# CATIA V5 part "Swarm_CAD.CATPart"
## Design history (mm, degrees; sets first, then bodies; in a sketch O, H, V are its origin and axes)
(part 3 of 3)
    distance L2 E3 = 15
    horizontal: L1 H, L3 H
    vertical: L2 V, L4 V
  Pad65: profile Sketch88, direction (0, 0, -1), length 192
  Sketch89 on end face of Pad51, origin (5055.8634, 0, -1213.8054), H (0, -1, 0), V (0.2334, 0, 0.9724)
    line L1 (-120, 1145.4414) -> (-59.7789, 1301.9134)
    line L2 (-59.7789, 1301.9134) -> (0, 1296.7668)
    point P3 (0, 1296.7668)
    line L3 (0, 1296.7668) -> (0, 1145.4414)
    line L4 (0, 1145.4414) -> (-120, 1145.4414)
    reference projected line E1 (-120, 1145.4414) -> (120, 1145.4414) from edge [face of Pad51 from Sketch66.L4 | end face of Pad51]
    reference projected line E2 (-78.762, 1252.5898) -> (-114.6804, 1159.2632) from edge [face of Pad51 from Sketch66.L3 | end face of Pad51]
    reference projected arc E3 centre (-0.0875, 1206.4414) radius 90 from (-0.0875, 1296.4414) to (-84.0815, 1238.7681) ccw from edge [face of Pad51 from Sketch66.A2 | end face of Pad51]
    length L2 = 60
    coincidence: P3 V, L4 E1, L1 E2
    vertical: L3 V
    horizontal: L4 H
    tangency: L2 E3
  Pad66: profile Sketch89, direction (-0.9724, 0, 0.2334), length 600
  Mirror32: of Pad66, about zx-plane
  Sketch90 on face of Mirror32, origin (4472.4414, 0, -1073.7382), H (0, -1, 0), V (0.2334, 0, 0.9724)
    line L1 (-120, 1145.4414) -> (-94.9835, 1210.4414)
    line L2 (-94.9835, 1210.4414) -> (94.9835, 1210.4414)
    line L3 (94.9835, 1210.4414) -> (120, 1145.4414)
    line L4 (120, 1145.4414) -> (-120, 1145.4414)
    reference projected line E1 (76.0903, 1145.4414) -> (-76.0903, 1145.4414) from edge [face of Mirror32 | face of Mirror2]
    reference projected line E2 (54.4593, 1315.7351) -> (114.6804, 1159.2632) from edge [face of Mirror32 | face of Mirror32]
    reference projected line E3 (-54.4593, 1315.7351) -> (-114.6804, 1159.2632) from edge [face of Pad66 from Sketch89.L1 | end face of Pad66]
    distance L2 L4 = 65
    horizontal: L2 H, L4 H
    coincidence: L4 E1, L3 E2, L1 E3
  Pad67: profile Sketch90, direction (-0.9724, 0, 0.2334), length 80
  Sketch91 on face of Pad34, origin (-2010, 0, 0), H (0, -1, 0), V (0, 0, 1)
    circle A1 centre (643.5, -160) radius 22.5
    reference projected circle E1 centre (643.5, -160) radius 22.5 from edge [face of Pad23 from Sketch30.A1 | face of Pad34]
    coincidence: A1 E1
  Pad68: profile Sketch91, direction (-1, 0, 0), length 60
  Sketch92 on face of Mirror30, origin (315.6888, -575.4594, -865.972), H (-0.8767, -0.481, 0), V (0.3833, -0.6987, 0.604)
    line L1 (-4371.7566, 1908.6399) -> (-4247.3214, 1946.2682)
    line L2 (-4247.3214, 1946.2682) -> (-4211.6687, 1828.366)
    line L3 (-4211.6687, 1828.366) -> (-4336.1039, 1790.7377)
    line L4 (-4336.1039, 1790.7377) -> (-4371.7566, 1908.6399)
    reference projected line E1 (-4398.7442, 1921.3735) -> (-4226.4493, 1973.4742) from edge [face of Mirror30 | face of Mirror30]
    reference projected line E2 (-4426.903, 2004.6358) -> (-4363.2245, 1794.0531) from edge [face of Mirror30 | face of Mirror30]
    reference projected line E3 (-4351.5135, 1765.1836) -> (-4179.2186, 1817.2842) from edge [face of Mirror30 | face of Mirror30]
    reference projected line E4 (-4231.9118, 1981.6804) -> (-4184.6811, 1825.4904) from edge [face of Mirror30 | face of Mirror30]
    distance L1 E1 = 20
    distance L4 E2 = 25
    distance L3 E3 = 20
    distance L2 E4 = 25
    perpendicularity: L2 L1
    parallelism: L3 L1, L4 L2
  Pocket21: profile Sketch92, direction (0.2905, -0.5296, -0.7969), length 40
  Mirror33: of Pocket21, about zx-plane
  Mirror34: of Pad68, about zx-plane
  Extract1: ExtractElem Mirror34
  Sketch93 on face of Mirror1, origin (0, 263.2631, 362.3506), H (-1, 0, 0), V (0, -0.809, 0.5878)
    construction line L1 through (0, 0) direction (1, 0)
    line L2 (-2844.2574, 144.728) -> (-1890, 144.728)
    construction line L3 through (0, 0) direction (0, 1)
    line L4 (-1890, 144.728) -> (-1890, -125.272)
    line L5 (-1890, -125.272) -> (-2240.2725, -125.272)
    line L6 (-2240.2725, -125.272) -> (-2240.2725, -35.272)
    line L7 (-2240.2725, -35.272) -> (-2558.5699, -35.272)
    line L8 (-2558.5699, -35.272) -> (-2558.5699, 54.728)
    line L9 (-2558.5699, 54.728) -> (-2844.2574, 54.728)
    line L10 (-2844.2574, 54.728) -> (-2844.2574, 144.728)
    point P1 (-1850, 144.728)
    line L11 (-1850, 144.728) -> (-782.5, 144.728)
    line L12 (-782.5, -125.272) -> (-1850, -125.272)
    line L13 (-782.5, 144.728) -> (-782.5, -125.272)
    line L14 (-1850, -125.272) -> (-1850, 144.728)
    line L15 (-1715.8627, -155.272) -> (-1715.8627, -245.272)
    line L16 (-1715.8627, -245.272) -> (-1433.2097, -245.272)
    line L17 (-1433.2097, -245.272) -> (-1433.2097, -335.272)
    line L18 (-1433.2097, -335.272) -> (-1069.0842, -335.272)
    line L19 (-1069.0842, -335.272) -> (-1069.0842, -425.272)
    line L20 (-1069.0842, -425.272) -> (-782.5, -425.272)
    line L21 (-782.5, -425.272) -> (-782.5, -155.272)
    point P2 (-602.5, 144.728)
    line L22 (-602.5, 144.728) -> (-317.271, 144.728)
    line L23 (-317.271, -125.272) -> (-602.5, -125.272)
    line L24 (-317.271, 144.728) -> (-317.271, -125.272)
    line L25 (-602.5, -125.272) -> (-602.5, 144.728)
    point P3 (-317.271, -125.272)
    line L26 (-2876.7362, -105.6676) -> (-1922.0492, -331.0454)
    line L27 (-1901.3708, -243.4531) -> (-2857.204, -17.8047)
    line L28 (-850.4962, -584.0124) -> (-1795.527, -360.9141)
    line L29 (-1774.8487, -273.3219) -> (-829.8179, -496.4201)
    line L30 (-1922.0492, -331.0454) -> (-1901.3708, -243.4531)
    line L31 (-1795.527, -360.9141) -> (-1774.8487, -273.3219)
    point P4 (-1901.3708, -243.4531)
    point P5 (-1890, -125.272)
    line L32 (-782.5, -155.272) -> (-1715.8627, -155.272)
    line L33 (-829.8179, -496.4201) -> (-850.4962, -584.0124)
    point P6 (-602.5, -155.272)
    line L34 (-602.5, -155.272) -> (-317.271, -155.272)
    line L35 (-317.271, -425.272) -> (-602.5, -425.272)
    line L36 (-317.271, -155.272) -> (-317.271, -425.272)
    line L37 (-602.5, -425.272) -> (-602.5, -155.272)
    point P7 (-317.271, -425.272)
    line L38 (-440, -456.272) -> (-40, -456.272)
    line L39 (-40, -571.272) -> (-440, -571.272)
    line L40 (-40, -456.272) -> (-40, -571.272)
    line L41 (-440, -571.272) -> (-440, -456.272)
    point P8 (-217.271, 144.728)
    line L42 (-217.271, 144.728) -> (832.729, 144.728)
    line L43 (832.729, -425.272) -> (-217.271, -425.272)
    line L44 (832.729, 144.728) -> (832.729, -425.272)
    line L45 (-217.271, -425.272) -> (-217.271, 144.728)
    point P9 (832.729, -425.272)
    point P10 (860, 144.728)
    line L46 (860, 144.728) -> (1910, 144.728)
    line L47 (1910, -425.272) -> (860, -425.272)
    line L48 (1910, 144.728) -> (1910, -425.272)
    line L49 (860, -425.272) -> (860, 144.728)
    point P11 (1910, -425.272)
    point P12 (310, -571.272)
    line L50 (310, -571.272) -> (1340, -571.272)
    line L51 (1340, -671.272) -> (310, -671.272)
    line L52 (1340, -571.272) -> (1340, -671.272)
    line L53 (310, -671.272) -> (310, -571.272)
    point P13 (310, -456.272)
    line L54 (310, -456.272) -> (530, -456.272)
    line L55 (530, -536.272) -> (310, -536.272)
    line L56 (530, -456.272) -> (530, -536.272)
    line L57 (310, -536.272) -> (310, -456.272)
    point P14 (630, -456.272)
    line L58 (630, -456.272) -> (850, -456.272)
    line L59 (850, -536.272) -> (630, -536.272)
    line L60 (850, -456.272) -> (850, -536.272)
    line L61 (630, -536.272) -> (630, -456.272)
    point P15 (850, -536.272)
    point P16 (950, -456.272)
    line L62 (950, -456.272) -> (1170, -456.272)
    line L63 (1170, -536.272) -> (950, -536.272)
    line L64 (1170, -456.272) -> (1170, -536.272)
    line L65 (950, -536.272) -> (950, -456.272)
    point P17 (1170, -536.272)
    point P18 (1270, -456.272)
    line L66 (1270, -456.272) -> (1490, -456.272)
    line L67 (1490, -536.272) -> (1270, -536.272)
    line L68 (1490, -456.272) -> (1490, -536.272)
    line L69 (1270, -536.272) -> (1270, -456.272)
    point P19 (1490, -536.272)
    point P20 (1170, -456.272)
    point P21 (0, 0)
    line L70 (-2857.204, -17.8047) -> (-2876.7362, -105.6676)
    distance L27 L26 = 90
    distance L29 L28 = 90
    distance L31 L30 = 130
    angle L30 L26 = 90
    distance L5 L2 = 270
    distance P5 P4 L1 = 11.3708
    length L8 = 90
    length L6 = 90
    distance L12 L11 = 270
    distance L32 L12 = 30
    distance L20 L32 = 270
    length L19 = 90
    length L17 = 90
    distance L21 L13 = 0
    angle L33 L28 = 90
    distance L14 L4 = 40
    distance L57 L56 = 220
    distance L61 L60 = 220
    distance L65 P20 = 220
    distance L69 L68 = 220
    distance L60 L65 = 100
    distance L64 L69 = 100
    distance L56 L61 = 100
    distance L55 L54 = 80
    distance L59 L50 = 35
    distance L45 L44 = 1050
    distance L49 L48 = 1050
    distance L45 L36 = 100
    horizontal: L2 L1, L5 L1, L7 L1, L9 L1, L11 L1, L12 L1, L16 L1, L18 L1, L20 L1, L22 L1, L23 L1, L34 L1, L35 L1, L38 L1, L39 L1, L42 L1, L43 L1, L46 L1, L47 L1, L50 L1, L51 L1, L54 L1, L55 L1, L58 L1, L59 L1, L62 L1, L63 L1, L66 L1, L67 L1
    vertical: L4 L3, L6 L3, L8 L3, L10 L3, L13 L3, L14 L3, L15 L3, L17 L3, L19 L3, L21 L3, L24 L3, L25 L3, L36 L3, L37 L3, L40 L3, L41 L3, L44 L3, L45 L3, L48 L3, L49 L3, L52 L3, L53 L3, L56 L3, L57 L3, L60 L3, L61 L3, L64 L3, L65 L3, L68 L3, L69 L3
    coincidence: P1 L2, P2 L2, P3 L12, P6 L25, P6 L32, P7 L24, P7 L20, P8 L2, P9 L35, P10 L2, P11 L35, P12 L39, P13 L53, P13 L38, P14 L38, P15 L55, P16 L38, P17 L55, P18 L38, P19 L55
  Pad69: profile Sketch93, direction (0, 0.5878, 0.809), length 10
  Sketch94 on end face of Pad69, origin (3403, 269.141, 370.4408), H (-0.5878, 0.6545, -0.4755), V (-0.809, -0.4755, 0.3455)
    point P1 (-825.75, -46.32)
    line L1 (-825.75, -46.32) -> (-113.815, 470.931)
    line L2 (-113.815, 470.931) -> (113.815, 470.931)
    line L3 (113.815, 470.931) -> (825.75, -46.32)
    point P4 (825.75, -46.32)
    line L4 (825.75, -46.32) -> (811.0554, -66.5454)
    point P5 (811.0554, -66.5454)
    line L5 (811.0554, -66.5454) -> (665, 39.57)
    point P6 (665, 39.57)
    line L6 (665, 39.57) -> (665, -300)
    line L7 (665, -300) -> (-665, -300)
    line L8 (-665, -300) -> (-665, 39.57)
    point P9 (-665, 39.57)
    line L9 (-665, 39.57) -> (-811.0554, -66.5454)
    point P10 (-811.0554, -66.5454)
    line L10 (-811.0554, -66.5454) -> (-825.75, -46.32)
    distance L7 H = 300
    distance P1 L7 = 253.68
    distance P4 L7 = 253.68
    distance L8 L6 = 1330
    distance L8 V = 665
    angle L1 V = 54
    angle L3 V = 54
    distance P1 P4 = 1651.5
    distance P6 P9 V = 0
    angle L5 L4 = 90
    distance P10 P5 V = 0
    distance L5 L3 = 25
    length L1 = 880
    horizontal: L2 H, L7 H
    vertical: L6 V, L8 V
    perpendicularity: L10 L1
    parallelism: L1 L9
  Mirror35: of Pad69, about zx-plane
  Sketch95 on end face of Pad69, origin (0, 269.141, 370.4408), H (-1, 0, 0), V (0, -0.809, 0.5878)
    line L1 (-2704.2574, 161.9212) -> (-2699.2574, 161.9212)
    line L2 (-2699.2574, 161.9212) -> (-2699.2574, -32.7041)
    line L3 (-2699.2574, -32.7041) -> (-2704.2574, -32.7041)
    line L4 (-2704.2574, -32.7041) -> (-2704.2574, 161.9212)
    line L5 (-2563.5699, -32.0096) -> (-2563.5699, 157.9904)
    line L6 (-2558.5699, 157.9904) -> (-2558.5699, -32.0096)
    line L7 (-2558.5699, -32.0096) -> (-2563.5699, -32.0096)
    line L8 (-2563.5699, 157.9904) -> (-2558.5699, 157.9904)
    reference projected line E1 (-2558.5699, 54.728) -> (-2558.5699, -35.272) from edge [face of Pad69 from Sketch93.L8 | end face of Pad69]
    line L9 (-2448.5699, -44.7326) -> (-2448.5699, 160)
    line L10 (-2443.5699, 148.3248) -> (-2443.5699, -41.6752)
    line L11 (-2448.5699, 160) -> (-2443.5699, 148.3248)
    line L12 (-2443.5699, -41.6752) -> (-2448.5699, -44.7326)
    line L13 (-2333.5699, -41.9996) -> (-2333.5699, 146.4384)
    line L14 (-2338.5699, 146.173) -> (-2338.5699, -41.8902)
    line L15 (-2333.5699, 146.4384) -> (-2338.5699, 146.173)
    line L16 (-2338.5699, -41.8902) -> (-2333.5699, -41.9996)
    point P17 (-2245.2725, 151.1255)
    line L17 (-2245.2725, 151.1255) -> (-2240.2725, 151.1255)
    line L18 (-2240.2725, 151.1255) -> (-2240.2725, -140.1003)
    line L19 (-2240.2725, -140.1003) -> (-2245.2725, -140.1003)
    line L20 (-2245.2725, -140.1003) -> (-2245.2725, 151.1255)
    line L21 (-2130.2725, 146.241) -> (-2125.2725, 146.241)
    line L22 (-2125.2725, 146.241) -> (-2125.2725, -142.1304)
    line L23 (-2125.2725, -142.1304) -> (-2130.2725, -142.1304)
    line L24 (-2130.2725, -142.1304) -> (-2130.2725, 146.241)
    line L25 (-2015.2725, 153.0203) -> (-2010.2725, 153.0203)
    line L26 (-2010.2725, 153.0203) -> (-2010.2725, -135.3512)
    line L27 (-2010.2725, -135.3512) -> (-2015.2725, -135.3512)
    line L28 (-2015.2725, -135.3512) -> (-2015.2725, 153.0203)
    line L29 (-1740, 148.9969) -> (-1735, 148.9969)
    line L30 (-1735, 148.9969) -> (-1735, -139.3745)
    line L31 (-1735, -139.3745) -> (-1740, -139.3745)
    line L32 (-1740, -139.3745) -> (-1740, 148.9969)
    line L33 (-1630, 155.7761) -> (-1625, 155.7761)
    line L34 (-1625, 155.7761) -> (-1625, -132.5953)
    line L35 (-1625, -132.5953) -> (-1630, -132.5953)
    line L36 (-1630, -132.5953) -> (-1630, 155.7761)
    line L37 (-1515, 148.9178) -> (-1510, 148.9178)
    line L38 (-1510, 148.9178) -> (-1510, -139.4537)
    line L39 (-1510, -139.4537) -> (-1515, -139.4537)
    line L40 (-1515, -139.4537) -> (-1515, 148.9178)
    line L41 (-1400, 148.4162) -> (-1395, 148.4162)
    line L42 (-1395, 148.4162) -> (-1395, -139.9552)
    line L43 (-1395, -139.9552) -> (-1400, -139.9552)
    line L44 (-1400, -139.9552) -> (-1400, 148.4162)
    line L45 (-1285, 149.7518) -> (-1289.0842, 149.7427)
    line L46 (-1289.0842, 149.7427) -> (-1289.0842, -138.6288)
    line L47 (-1289.0842, -138.6288) -> (-1285, -138.6288)
    line L48 (-1285, -138.6288) -> (-1285, 149.7518)
    line L49 (-1179.0842, 149.2411) -> (-1184.0842, 149.2411)
    line L50 (-1184.0842, 149.2411) -> (-1184.0842, -139.1303)
    line L51 (-1184.0842, -139.1303) -> (-1179.0842, -139.1303)
    line L52 (-1179.0842, -139.1303) -> (-1179.0842, 149.2411)
    line L53 (-1074.0842, 156.5219) -> (-1069.0842, 156.5219)
    line L54 (-1069.0842, 156.5219) -> (-1069.0842, -131.8496)
    line L55 (-1069.0842, -131.8496) -> (-1074.0842, -131.8496)
    line L56 (-1074.0842, -131.8496) -> (-1074.0842, 156.5219)
    line L57 (-959.0842, 151.8091) -> (-954.0842, 151.8091)
    line L58 (-954.0842, 151.8091) -> (-954.0842, -136.5624)
    line L59 (-954.0842, -136.5624) -> (-959.0842, -136.5624)
    line L60 (-959.0842, -136.5624) -> (-959.0842, 151.8091)
    line L61 (-864.0842, 151.3075) -> (-859.0842, 151.3075)
    line L62 (-859.0842, 151.3075) -> (-859.0842, -137.0639)
    line L63 (-859.0842, -137.0639) -> (-864.0842, -137.0639)
    line L64 (-864.0842, -137.0639) -> (-864.0842, 151.3075)
    reference projected line E2 (-2844.2574, 144.728) -> (-2844.2574, 54.728) from edge [face of Pad69 from Sketch93.L10 | end face of Pad69]
    reference projected line E3 (-2240.2725, -35.272) -> (-2240.2725, -125.272) from edge [face of Pad69 from Sketch93.L6 | end face of Pad69]
    reference projected line E4 (-1850, 144.728) -> (-1850, -125.272) from edge [face of Pad69 from Sketch93.L14 | end face of Pad69]
    point P65 (-1630, -142.1304)
    line L65 (-1630, -142.1304) -> (-1625, -142.1304)
    line L66 (-1625, -142.1304) -> (-1625, -260)
    line L67 (-1625, -260) -> (-1630, -260)
    line L68 (-1630, -260) -> (-1630, -142.1304)
    point P67 (-1625, -260)
    point P69 (-1515, -146.3943)
    line L69 (-1515, -146.3943) -> (-1510, -146.3943)
    line L70 (-1510, -146.3943) -> (-1510, -310)
    line L71 (-1510, -310) -> (-1515, -310)
    line L72 (-1515, -310) -> (-1515, -146.3943)
    point P71 (-1510, -310)
    point P73 (-1400, -146.3943)
    line L73 (-1400, -146.3943) -> (-1395, -146.3943)
    line L74 (-1395, -146.3943) -> (-1395, -350)
    line L75 (-1395, -350) -> (-1400, -350)
    line L76 (-1400, -350) -> (-1400, -146.3943)
    point P75 (-1395, -350)
    point P77 (-1285, -146.3943)
    line L77 (-1285, -146.3943) -> (-1289.0842, -146.3943)
    line L78 (-1289.0842, -146.3943) -> (-1289.0842, -360)
    line L79 (-1289.0842, -360) -> (-1285, -360)
    line L80 (-1285, -360) -> (-1285, -146.3943)
    point P79 (-1289.0842, -360)
    point P81 (-1179.0842, -146.3943)
    line L81 (-1179.0842, -146.3943) -> (-1184.0842, -146.3943)
    line L82 (-1184.0842, -146.3943) -> (-1184.0842, -370)
    line L83 (-1184.0842, -370) -> (-1179.0842, -370)
    line L84 (-1179.0842, -370) -> (-1179.0842, -146.3943)
    point P83 (-1184.0842, -370)
    point P85 (-1069.0842, -142.1304)
    line L85 (-1069.0842, -142.1304) -> (-1074.0842, -142.1304)
    line L86 (-1074.0842, -142.1304) -> (-1074.0842, -400)
    line L87 (-1074.0842, -400) -> (-1069.0842, -400)
    line L88 (-1069.0842, -400) -> (-1069.0842, -142.1304)
    reference projected line E5 (-1069.0842, -335.272) -> (-1069.0842, -425.272) from edge [face of Pad69 from Sketch93.L19 | end face of Pad69]
    point P89 (-959.0842, -146.3943)
    line L89 (-959.0842, -146.3943) -> (-954.0842, -146.3943)
    line L90 (-954.0842, -146.3943) -> (-954.0842, -430)
    line L91 (-954.0842, -430) -> (-959.0842, -430)
    line L92 (-959.0842, -430) -> (-959.0842, -146.3943)
    point P91 (-954.0842, -430)
    point P93 (-864.0842, -146.3943)
    line L93 (-864.0842, -146.3943) -> (-859.0842, -146.3943)
    line L94 (-859.0842, -146.3943) -> (-859.0842, -450)
    line L95 (-859.0842, -450) -> (-864.0842, -450)
    line L96 (-864.0842, -450) -> (-864.0842, -146.3943)
    point P95 (-859.0842, -450)
    point P97 (-510, -146.3943)
    line L97 (-510, -132.9567) -> (-510, 155.4147)
    line L98 (-505, -146.3943) -> (-505, -426.3943)
    line L99 (-510, -426.3943) -> (-510, -146.3943)
    line L100 (-505, 155.4147) -> (-505, -132.9567)
    point P98 (-505, -426.3943)
    point P99 (-415, -146.3943)
    line L101 (-415, -133.4583) -> (-415, 154.9132)
    line L102 (-415, -146.3943) -> (-410, -146.3943)
    line L103 (-410, -443.753) -> (-415, -443.753)
    line L104 (-410, -146.3943) -> (-410, -443.753)
    line L105 (-415, -443.753) -> (-415, -146.3943)
    line L106 (-410, 154.9132) -> (-410, -133.4583)
    point P100 (-410, -443.753)
    line L107 (-510, 155.4147) -> (-505, 155.4147)
    line L108 (-505, -132.9567) -> (-510, -132.9567)
    line L109 (-415, 154.9132) -> (-410, 154.9132)
    line L110 (-410, -133.4583) -> (-415, -133.4583)
    line L111 (-510, -146.3943) -> (-505, -146.3943)
    line L112 (-505, -426.3943) -> (-510, -426.3943)
    point P113 (-320, -450)
    line L113 (-320, -450) -> (-315, -450)
    line L114 (-315, -450) -> (-315, -590)
    line L115 (-315, -590) -> (-320, -590)
    line L116 (-320, -590) -> (-320, -450)
    line L117 (-185, -442.0433) -> (-185, -582.0433)
    line L118 (-190, -582.0433) -> (-190, -442.0433)
    line L119 (-190, -442.0433) -> (-185, -442.0433)
    line L120 (-185, -582.0433) -> (-190, -582.0433)
    point P121 (-107.271, 152.384)
    line L121 (-107.271, 152.384) -> (-102.271, 152.384)
    line L122 (-102.271, 152.384) -> (-102.271, -443.753)
    line L123 (-102.271, -443.753) -> (-107.271, -443.753)
    line L124 (-107.271, -443.753) -> (-107.271, 152.384)
    point P123 (-102.271, -443.753)
    line L125 (-2.271, 150.9154) -> (2.729, 150.227)
    line L126 (2.729, 150.227) -> (2.729, -445.91)
    line L127 (2.729, -445.91) -> (-2.271, -445.2216)
    line L128 (-2.271, -445.2216) -> (-2.271, 150.9154)
    line L129 (102.729, 168.1314) -> (107.729, 168.1314)
    line L130 (107.729, 168.1314) -> (107.729, -428.0057)
    line L131 (107.729, -428.0057) -> (102.729, -428.0057)
    line L132 (102.729, -428.0057) -> (102.729, 168.1314)
    line L133 (207.729, 148.7572) -> (212.729, 148.7572)
    line L134 (212.729, 148.7572) -> (212.729, -447.3798)
    line L135 (212.729, -447.3798) -> (207.729, -447.3798)
    line L136 (207.729, -447.3798) -> (207.729, 148.7572)
    line L137 (305, 152.125) -> (310, 152.125)
    line L138 (310, 152.125) -> (310, -444.0121)
    line L139 (310, -444.0121) -> (305, -444.0121)
    line L140 (305, -444.0121) -> (305, 152.125)
    line L141 (410, 150.008) -> (415, 150.008)
    line L142 (415, 150.008) -> (415, -715.1164)
    line L143 (415, -715.1164) -> (410, -715.1164)
    line L144 (410, -715.1164) -> (410, 150.008)
    reference projected line E6 (-217.271, 144.728) -> (-217.271, -425.272) from edge [face of Pad69 from Sketch93.L45 | end face of Pad69]
    reference projected line E7 (310, -456.272) -> (310, -536.272) from edge [face of Pad69 from Sketch93.L57 | end face of Pad69]
    line L145 (530, -719.2029) -> (530, 145.9214)
    line L146 (535, 145.9214) -> (535, -719.2029)
    line L147 (530, 145.9214) -> (535, 145.9214)
    line L148 (535, -719.2029) -> (530, -719.2029)
    line L149 (625, -724.6691) -> (625, 140.4553)
    line L150 (630, 139.2595) -> (630, -725.8648)
    line L151 (625, 140.4553) -> (630, 139.2595)
    line L152 (630, -725.8648) -> (625, -724.6691)
    line L153 (727.729, -705.94) -> (727.729, 159.1844)
    line L154 (732.729, 159.1844) -> (732.729, -705.94)
    line L155 (727.729, 159.1844) -> (732.729, 159.1844)
    line L156 (732.729, -705.94) -> (727.729, -705.94)
    line L157 (945, -717.3063) -> (945, 147.8181)
    line L158 (950, 155.1531) -> (950, -709.9713)
    line L159 (945, 147.8181) -> (950, 155.1531)
    line L160 (950, -709.9713) -> (945, -717.3063)
    line L161 (1065, -717.7143) -> (1065, 147.41)
    line L162 (1070, 147.41) -> (1070, -717.7143)
    line L163 (1065, 147.41) -> (1070, 147.41)
    line L164 (1070, -717.7143) -> (1065, -717.7143)
    line L165 (1170, -715.4619) -> (1170, 149.6625)
    line L166 (1175, 148.1014) -> (1175, -717.023)
    line L167 (1170, 149.6625) -> (1175, 148.1014)
    line L168 (1175, -717.023) -> (1170, -715.4619)
    line L169 (1265, -716.6782) -> (1265, 148.4462)
    line L170 (1270, 148.5427) -> (1270, -716.5816)
    line L171 (1265, 148.4462) -> (1270, 148.5427)
    line L172 (1270, -716.5816) -> (1265, -716.6782)
    line L173 (1385, -716.7043) -> (1385, 148.4201)
    line L174 (1390, 148.4201) -> (1390, -716.7043)
    line L175 (1385, 148.4201) -> (1390, 148.4201)
    line L176 (1390, -716.7043) -> (1385, -716.7043)
    line L177 (1490, -570) -> (1490, 156.8319)
    line L178 (1495, 156.8319) -> (1495, -570)
    line L179 (1490, 156.8319) -> (1495, 156.8319)
    line L180 (1495, -570) -> (1490, -570)
    line L181 (1595, -510) -> (1595, 155.2945)
    line L182 (1600, 155.2945) -> (1600, -510)
    line L183 (1595, 155.2945) -> (1600, 155.2945)
    line L184 (1600, -510) -> (1595, -510)
    line L185 (1700, -520) -> (1700, 156.0891)
    line L186 (1705, 156.0891) -> (1705, -520)
    line L187 (1700, 156.0891) -> (1705, 156.0891)
    line L188 (1705, -520) -> (1700, -520)
    line L189 (1805, -470) -> (1805, 145.7765)
    line L190 (1810, 145.7765) -> (1810, -470)
    line L191 (1805, 145.7765) -> (1810, 145.7765)
    line L192 (1810, -470) -> (1805, -470)
    reference projected line E8 (1910, -425.272) -> (1910, 144.728) from edge [face of Pad69 from Sketch93.L48 | end face of Pad69]
    reference projected line E9 (1270, -456.272) -> (1270, -536.272) from edge [face of Pad69 from Sketch93.L69 | end face of Pad69]
    reference projected line E10 (1170, -536.272) -> (1170, -456.272) from edge [face of Pad69 from Sketch93.L64 | end face of Pad69]
    reference projected line E11 (950, -456.272) -> (950, -536.272) from edge [face of Pad69 from Sketch93.L65 | end face of Pad69]
    reference projected line E12 (832.729, -425.272) -> (832.729, 144.728) from edge [face of Pad69 from Sketch93.L44 | end face of Pad69]
    reference projected line E13 (630, -456.272) -> (630, -536.272) from edge [face of Pad69 from Sketch93.L61 | end face of Pad69]
    reference projected line E14 (530, -536.272) -> (530, -456.272) from edge [face of Pad69 from Sketch93.L56 | end face of Pad69]
    point P193 (830, -570)
    line L193 (830, -570) -> (835, -570)
    line L194 (835, -570) -> (835, -690)
    line L195 (835, -690) -> (830, -690)
    line L196 (830, -690) -> (830, -570)
    line L197 (-2758.075, -32.7041) -> (-2782.6271, -143.1482)
    line L198 (-2782.6271, -143.1482) -> (-2777.505, -143.1482)
    line L199 (-2777.505, -143.1482) -> (-2752.953, -32.7041)
    line L200 (-2752.953, -32.7041) -> (-2758.075, -32.7041)
    reference projected line E15 (-2857.204, -17.8047) -> (-2876.7362, -105.6676) from edge [face of Pad69 from Sketch93.L70 | end face of Pad69]
    line L201 (-2680.6218, -168.1498) -> (-2675.4997, -168.1498)
    line L202 (-2656.0698, -57.7057) -> (-2680.6218, -168.1498)
    line L203 (-2675.4997, -168.1498) -> (-2650.9477, -57.7057)
    line L204 (-2650.9477, -57.7057) -> (-2656.0698, -57.7057)
    line L205 (-2578.7518, -193.7597) -> (-2573.6297, -193.7597)
    line L206 (-2554.1997, -83.3156) -> (-2578.7518, -193.7597)
    line L207 (-2573.6297, -193.7597) -> (-2549.0777, -83.3156)
    line L208 (-2549.0777, -83.3156) -> (-2554.1997, -83.3156)
    line L209 (-2475.3171, -212.3314) -> (-2470.1951, -212.3314)
    line L210 (-2450.7651, -101.8873) -> (-2475.3171, -212.3314)
    line L211 (-2470.1951, -212.3314) -> (-2445.643, -101.8873)
    line L212 (-2445.643, -101.8873) -> (-2450.7651, -101.8873)
    line L213 (-2373.5352, -238.3377) -> (-2368.4131, -238.3377)
    line L214 (-2348.9832, -127.8936) -> (-2373.5352, -238.3377)
    line L215 (-2368.4131, -238.3377) -> (-2343.8611, -127.8936)
    line L216 (-2343.8611, -127.8936) -> (-2348.9832, -127.8936)
    line L217 (-2271.9965, -265.438) -> (-2266.8744, -265.438)
    line L218 (-2247.4445, -154.9939) -> (-2271.9965, -265.438)
    line L219 (-2266.8744, -265.438) -> (-2242.3224, -154.9939)
    line L220 (-2242.3224, -154.9939) -> (-2247.4445, -154.9939)
    line L221 (-2168.6292, -284.3126) -> (-2163.5071, -284.3126)
    line L222 (-2144.0772, -173.8685) -> (-2168.6292, -284.3126)
    line L223 (-2163.5071, -284.3126) -> (-2138.9551, -173.8685)
    line L224 (-2138.9551, -173.8685) -> (-2144.0772, -173.8685)
    line L225 (-2075.7233, -304.1648) -> (-2070.6012, -304.1648)
    line L226 (-2051.1713, -193.7207) -> (-2075.7233, -304.1648)
    line L227 (-2070.6012, -304.1648) -> (-2046.0492, -193.7207)
    line L228 (-2046.0492, -193.7207) -> (-2051.1713, -193.7207)
    line L229 (-1998.4193, -328.1813) -> (-1993.2972, -328.1813)
    line L230 (-1973.8672, -217.7372) -> (-1998.4193, -328.1813)
    line L231 (-1993.2972, -328.1813) -> (-1967.3022, -218.0679)
    line L232 (-1967.3022, -218.0679) -> (-1973.8672, -217.7372)
    reference projected line E16 (-1922.0492, -331.0454) -> (-1901.3708, -243.4531) from edge [face of Pad69 from Sketch93.L30 | end face of Pad69]
    line L233 (-1708.9037, -397.9729) -> (-1703.7816, -397.9729)
    line L234 (-1605.5364, -416.8476) -> (-1600.4144, -416.8476)
    line L235 (-1512.6305, -436.6997) -> (-1507.5085, -436.6997)
    line L236 (-1435.3265, -460.7162) -> (-1430.2044, -460.7162)
    line L237 (-1703.7816, -397.9729) -> (-1679.2296, -287.5288)
    line L238 (-1580.9844, -306.4035) -> (-1605.5364, -416.8476)
    line L239 (-1600.4144, -416.8476) -> (-1575.8623, -306.4035)
    line L240 (-1488.0785, -326.2557) -> (-1512.6305, -436.6997)
    line L241 (-1684.3517, -287.5288) -> (-1708.9037, -397.9729)
    line L242 (-1679.2296, -287.5288) -> (-1684.3517, -287.5288)
    line L243 (-1575.8623, -306.4035) -> (-1580.9844, -306.4035)
    line L244 (-1507.5085, -436.6997) -> (-1482.9564, -326.2557)
    line L245 (-1482.9564, -326.2557) -> (-1488.0785, -326.2557)
    line L246 (-1410.7744, -350.2721) -> (-1435.3265, -460.7162)
    line L247 (-1430.2044, -460.7162) -> (-1404.2094, -350.6028)
    line L248 (-1404.2094, -350.6028) -> (-1410.7744, -350.2721)
    line L249 (-1349.0488, -481.0968) -> (-1343.9268, -481.0968)
    line L250 (-1245.6815, -499.9714) -> (-1240.5595, -499.9714)
    line L251 (-1152.7756, -519.8236) -> (-1147.6536, -519.8236)
    line L252 (-1075.4716, -543.8401) -> (-1070.3495, -543.8401)
    line L253 (-1343.9268, -481.0968) -> (-1319.3747, -370.6527)
    line L254 (-1221.1295, -389.5273) -> (-1245.6815, -499.9714)
    line L255 (-1240.5595, -499.9714) -> (-1216.0074, -389.5273)
    line L256 (-1128.2236, -409.3795) -> (-1152.7756, -519.8236)
    line L257 (-1324.4968, -370.6527) -> (-1349.0488, -481.0968)
    line L258 (-1319.3747, -370.6527) -> (-1324.4968, -370.6527)
    line L259 (-1216.0074, -389.5273) -> (-1221.1295, -389.5273)
    line L260 (-1147.6536, -519.8236) -> (-1123.1016, -409.3795)
    line L261 (-1123.1016, -409.3795) -> (-1128.2236, -409.3795)
    line L262 (-1050.9196, -433.396) -> (-1075.4716, -543.8401)
    line L263 (-1070.3495, -543.8401) -> (-1044.3545, -433.7267)
    line L264 (-1044.3545, -433.7267) -> (-1050.9196, -433.396)
    line L265 (-1003.8652, -564.4387) -> (-998.7431, -564.4387)
    line L266 (-926.5611, -588.4552) -> (-921.4391, -588.4552)
    line L267 (-979.3131, -453.9946) -> (-1003.8652, -564.4387)
    line L268 (-998.7431, -564.4387) -> (-974.1911, -453.9946)
    line L269 (-974.1911, -453.9946) -> (-979.3131, -453.9946)
    line L270 (-902.0091, -478.0111) -> (-926.5611, -588.4552)
    line L271 (-921.4391, -588.4552) -> (-895.444, -478.3418)
    line L272 (-895.444, -478.3418) -> (-902.0091, -478.0111)
    reference projected line E17 (-1433.2097, -245.272) -> (-1433.2097, -335.272) from edge [face of Pad69 from Sketch93.L17 | end face of Pad69]
    distance L2 L4 = 5
    distance L6 E1 = 0
    distance L20 L18 = 5
    distance L4 E2 = 140
    distance L5 L2 = 135.6875
    distance L9 L6 = 110
    distance L13 L10 = 110
    distance L10 L9 = 5
    distance L14 L13 = 5
    distance L18 E3 = 0
    distance L24 L18 = 110
    distance L28 L22 = 110
    distance L26 L28 = 5
    distance L32 E4 = 110
    distance L30 L32 = 5
    distance L36 L32 = 110
    distance L40 L34 = 110
    distance L44 L38 = 110
    distance L48 L42 = 110
    distance L52 L46 = 110
    distance L56 L50 = 110
    distance L60 L54 = 110
    distance L64 L58 = 90
    distance L88 L86 = 5
    distance L88 E5 = 0
    distance L56 L86 = 0
    distance L52 L50 = 5
    distance L114 L116 = 5
    distance L124 E6 = 110
    distance L122 L124 = 5
    distance L128 L126 = 5
    distance L128 L122 = 100
    distance L132 L130 = 5
    distance L132 L126 = 100
    distance L136 L134 = 5
    distance L136 L130 = 100
    distance L140 L138 = 5
    distance L140 E7 = 5
    distance L144 L138 = 100
    distance L142 L144 = 5
    distance L146 L145 = 5
    distance L150 L149 = 5
    distance L154 L153 = 5
    distance L158 L157 = 5
    distance L162 L161 = 5
    distance L166 L165 = 5
    distance L170 L169 = 5
    distance L174 L173 = 5
    distance L178 L177 = 5
    distance L182 L181 = 5
    distance L186 L185 = 5
    distance L190 L189 = 5
    distance L190 E8 = 100
    distance L186 L189 = 100
    distance L182 L185 = 100
    distance L178 L181 = 100
    distance L174 L177 = 100
    distance L170 E9 = 0
    distance L165 E10 = 0
    distance L162 L165 = 100
    distance L158 E11 = 0
    distance L154 E12 = 100
    distance L150 E13 = 0
    distance L145 E14 = 0
    distance L196 L194 = 5
    distance L197 L199 = 5
    distance L200 L198 = 110.4441
    distance L197 E15 = 100
    distance L202 L199 = 100
    distance L206 L203 = 100
    distance L210 L207 = 100
    distance L214 L211 = 100
    distance L218 L215 = 100
    distance L222 L219 = 100
    distance L226 L223 = 90
    distance L231 E16 = 70
    distance L238 L237 = 100
    distance L240 L239 = 90
    distance L254 L253 = 100
    distance L256 L255 = 90
    distance L76 E17 = 33.2097
    horizontal: L1 H, L3 H, L17 H, L19 H, L65 H, L67 H, L69 H, L71 H, L73 H, L75 H, L77 H, L79 H, L81 H, L83 H, L85 H, L87 H, L89 H, L91 H, L93 H, L95 H, L102 H, L103 H, L113 H, L115 H, L121 H, L123 H, L193 H, L195 H, L198 H, L201 H, L205 H, L209 H, L213 H, L217 H, L221 H, L225 H, L229 H, L233 H, L234 H, L235 H, L236 H, L249 H, L250 H, L251 H, L252 H, L265 H, L266 H
    vertical: L2 V, L4 V, L18 V, L20 V, L66 V, L68 V, L70 V, L72 V, L74 V, L76 V, L78 V, L80 V, L82 V, L84 V, L86 V, L88 V, L90 V, L92 V, L94 V, L96 V, L98 V, L99 V, L104 V, L105 V, L114 V, L116 V, L117 V, L118 V, L122 V, L124 V, L194 V, L196 V
    coincidence: P17 L15, P65 L36, P65 L23, P67 L34, P69 L40, P71 L38, P73 L69, P73 L44, P75 L42, P77 L69, P77 L48, P79 L46, P81 L69, P81 L52, P83 L50, P85 L23, P89 L69, P89 L60, P91 L58, P93 L69, P93 L64, P95 L62, P97 L69, P97 L97, P98 L100, P99 L69, P99 L101, P100 L106, P113 L95, P121 L45, P123 L103, P193 L180
  Pocket22: profile Sketch95, direction (0, -0.5878, -0.809), length 10
  Mirror36: of Pocket22, about zx-plane
  Sketch96 on end face of Pad69, origin (0, 269.141, 370.4408), H (-1, 0, 0), V (0, -0.809, 0.5878)
    line L1 (-2860, 99.728) -> (1930, 99.728)
    line L2 (1930, 99.728) -> (1930, 94.728)
    line L3 (1930, 94.728) -> (-2860, 94.728)
    line L4 (-2860, 94.728) -> (-2860, 99.728)
    reference projected line E1 (-2844.2574, 54.728) -> (-2558.5699, 54.728) from edge [face of Pad69 from Sketch93.L9 | end face of Pad69]
    line L5 (-2570, 55) -> (1940, 55)
    line L6 (1940, 55) -> (1940, 50)
    line L7 (1940, 50) -> (-2570, 50)
    line L8 (-2570, 50) -> (-2570, 55)
    point P9 (7.9407, -80)
    line L9 (-2562.0593, 10) -> (1947.9407, 10)
    line L10 (1947.9407, 10) -> (1947.9407, 5)
    line L11 (1947.9407, 5) -> (-2562.0593, 5)
    line L12 (-2562.0593, 5) -> (-2562.0593, 10)
    point P14 (320.9791, -120)
    line L13 (-2249.0209, -35) -> (2260.9791, -35)
    line L14 (2260.9791, -35) -> (2260.9791, -40)
    line L15 (2260.9791, -40) -> (-2249.0209, -40)
    line L16 (-2249.0209, -40) -> (-2249.0209, -35)
    point P19 (726.8307, -250)
    line L17 (-1843.1693, -195.272) -> (2666.8307, -195.272)
    line L18 (2666.8307, -195.272) -> (2666.8307, -200.272)
    line L19 (2666.8307, -200.272) -> (-1843.1693, -200.272)
    line L20 (-1843.1693, -200.272) -> (-1843.1693, -195.272)
    point P24 (1025.3837, -300)
    line L21 (-1544.6163, -245.272) -> (2965.3837, -245.272)
    line L22 (2965.3837, -245.272) -> (2965.3837, -250.272)
    line L23 (2965.3837, -250.272) -> (-1544.6163, -250.272)
    line L24 (-1544.6163, -250.272) -> (-1544.6163, -245.272)
    point P29 (1215.4979, -400)
    line L25 (-1354.5021, -335.272) -> (3155.4979, -335.272)
    line L26 (3155.4979, -335.272) -> (3155.4979, -340.272)
    line L27 (3155.4979, -340.272) -> (-1354.5021, -340.272)
    line L28 (-1354.5021, -340.272) -> (-1354.5021, -335.272)
    reference projected line E2 (-782.5, -155.272) -> (-1715.8627, -155.272) from edge [face of Pad69 from Sketch93.L32 | end face of Pad69]
    reference projected line E3 (-1715.8627, -245.272) -> (-1433.2097, -245.272) from edge [face of Pad69 from Sketch93.L16 | end face of Pad69]
    point P34 (-2.5256, -120)
    line L29 (-2259.4872, -80) -> (2250.5128, -80)
    line L30 (2250.5128, -80) -> (2250.5128, -85)
    line L31 (2250.5128, -85) -> (-2259.4872, -85)
    line L32 (-2259.4872, -85) -> (-2259.4872, -80)
    point P39 (928.5636, -245)
    line L33 (-1451.3221, -290.272) -> (3058.6779, -290.272)
    line L34 (3058.6779, -290.272) -> (3058.6779, -295.272)
    line L35 (3058.6779, -295.272) -> (-1451.3221, -295.272)
    line L36 (-1451.3221, -295.272) -> (-1451.3221, -290.272)
    point P44 (1206.6844, -330)
    line L37 (-1173.2013, -375.272) -> (3336.7987, -375.272)
    line L38 (3336.7987, -375.272) -> (3336.7987, -380.272)
    line L39 (3336.7987, -380.272) -> (-1173.2013, -380.272)
    line L40 (-1173.2013, -380.272) -> (-1173.2013, -375.272)
    point P49 (1905.8732, -440)
    line L41 (-474.0125, -496.272) -> (4035.9875, -496.272)
    line L42 (4035.9875, -496.272) -> (4035.9875, -501.272)
    line L43 (4035.9875, -501.272) -> (-474.0125, -501.272)
    line L44 (-474.0125, -501.272) -> (-474.0125, -496.272)
    point P54 (1909.7751, -500)
    line L45 (-470.1107, -536.272) -> (4039.8893, -536.272)
    line L46 (4039.8893, -536.272) -> (4039.8893, -541.272)
    line L47 (4039.8893, -541.272) -> (-470.1107, -541.272)
    line L48 (-470.1107, -541.272) -> (-470.1107, -536.272)
    point P59 (2397.0821, -575)
    line L49 (17.1964, -611.272) -> (4527.1964, -611.272)
    line L50 (4527.1964, -611.272) -> (4527.1964, -616.272)
    line L51 (4527.1964, -616.272) -> (17.1964, -616.272)
    line L52 (17.1964, -616.272) -> (17.1964, -611.272)
    reference projected line E4 (-1433.2097, -335.272) -> (-1069.0842, -335.272) from edge [face of Pad69 from Sketch93.L18 | end face of Pad69]
    reference projected line E5 (-40, -456.272) -> (-440, -456.272) from edge [face of Pad69 from Sketch93.L38 | end face of Pad69]
    reference projected line E6 (310, -536.272) -> (530, -536.272) from edge [face of Pad69 from Sketch93.L55 | end face of Pad69]
    reference projected line E7 (1340, -571.272) -> (310, -571.272) from edge [face of Pad69 from Sketch93.L50 | end face of Pad69]
    line L53 (-250, -135) -> (3790, -135)
    line L54 (3790, -135) -> (3790, -140)
    line L55 (3790, -140) -> (-250, -140)
    line L56 (-250, -140) -> (-250, -135)
    line L57 (-2877.493, -54.1145) -> (-2877.493, -59.252)
    line L58 (-2877.493, -59.252) -> (-807.1964, -547.9974)
    line L59 (-807.1964, -547.9974) -> (-819.9894, -539.8399)
    line L60 (-819.9894, -539.8399) -> (-2877.493, -54.1145)
    reference projected line E8 (-1901.3708, -243.4531) -> (-2857.204, -17.8047) from edge [face of Pad69 from Sketch93.L27 | end face of Pad69]
    distance L1 L3 = 5
    distance L3 E1 = 40
    distance L5 L7 = 5
    distance L9 L7 = 40
    distance L13 L11 = 40
    distance L17 E2 = 40
    distance L21 E3 = 0
    distance L29 L15 = 40
    distance L33 L23 = 40
    distance L25 E4 = 0
    distance L37 L25 = 40
    distance L41 E5 = 40
    distance L45 E6 = 0
    distance L49 E7 = 40
    distance L53 L55 = 5
    distance L53 L31 = 50
    distance L60 L58 = 5
    distance L60 E8 = 40
    horizontal: L1 H, L3 H, L5 H, L7 H, L53 H, L55 H
    vertical: L2 V, L4 V, L6 V, L8 V, L54 V, L56 V, L57 V
  Pocket23: profile Sketch96, direction (0, -0.5878, -0.809), length 10
  Mirror37: of Pocket23, about zx-plane
  Pad70: profile Sketch3, direction (0, -0.5878, -0.809), length 4945.11
  Pad71: profile Sketch94, direction (0, -0.5878, -0.809), length 4945.11
Current feature: Mirror37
